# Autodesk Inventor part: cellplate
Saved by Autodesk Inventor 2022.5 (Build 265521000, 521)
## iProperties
Created: 2024-05
Part Number: cellplate
Material: Generic
Document SubType Name: Modeling
Designer: AdminForWorker
Density: 1 g/cm^3
Appearance: Default
Title: cellplate
Author: AdminForWorker
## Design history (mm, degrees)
feature "cellplate_with_ring"
feature "cellplate_normal"
feature "cellplate_complete"
body "Solid1"
body "Solid2"
body "Solid3"
